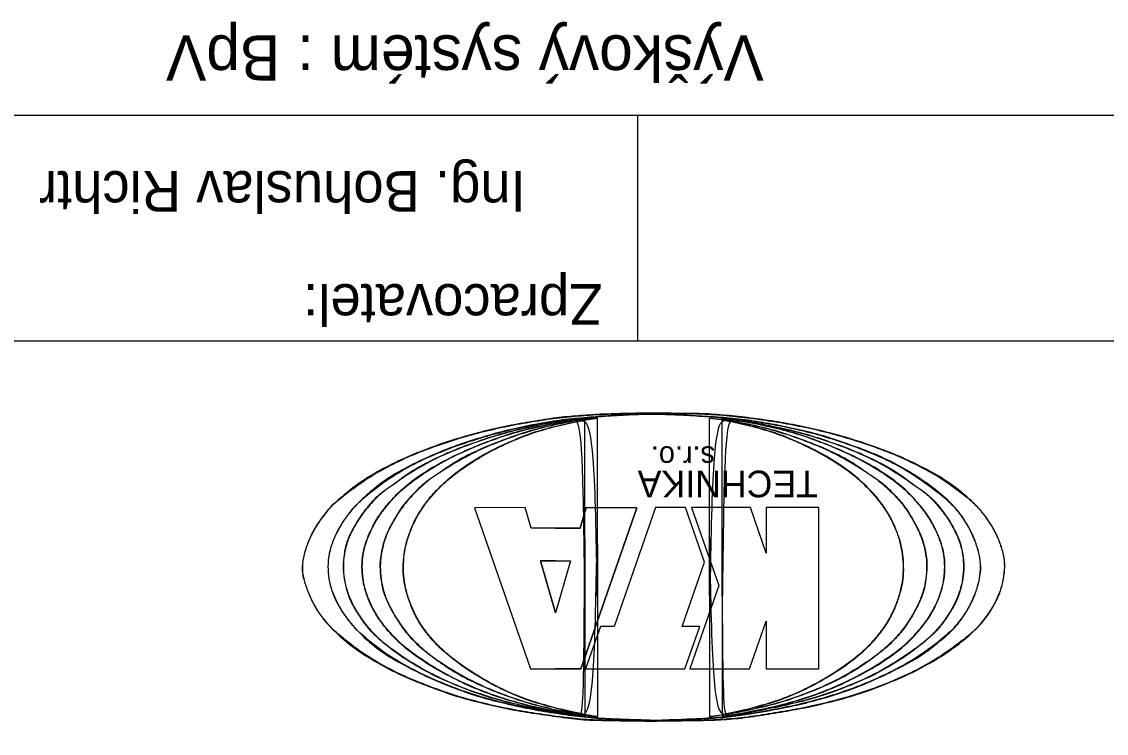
# Model space of a CAD drawing. Extents: x -728476.8 to -728424.3, y -1073086.9 to -1073012.7.
# Drawn here: x -728468.69 to -728456.69, y -1073042.49 to -1073034.62 of the extents above; entities that cross this region are included whole.
import ezdxf

# ---------------------------------------------------------------- set-up
doc = ezdxf.new("R2010")
doc.units = 0
doc.layers.add('A1_OBVOD Spravy železnic', color=7, linetype='Continuous')
doc.layers.add('B6_JŽM', color=7, linetype='Continuous')

msp = doc.modelspace()

# ---------------------------------------------------------------- linework, layer by layer
at = {"layer": 'A1_OBVOD Spravy železnic'}
for p, q in [((-728461.876, -1073035.654), (-728461.876, -1073038.154)), ((-728429.288, -1073038.154), (-728471.788, -1073038.154))]:
    msp.add_line(p, q, dxfattribs=at)
msp.add_lwpolyline([(-728429.288, -1073048.154), (-728471.788, -1073048.154), (-728471.788, -1073035.654), (-728429.288, -1073035.654)], close=True, dxfattribs=at)
at = {"layer": 'B6_JŽM'}
for p, q in [((-728462.947, -1073040.587), (-728462.781, -1073040.587)), ((-728462.781, -1073041.161), (-728462.947, -1073040.587))]:
    msp.add_line(p, q, dxfattribs=at)
for points in [[(-728462.781, -1073040.225), (-728463.051, -1073040.225), (-728463.117, -1073039.997), (-728463.68, -1073039.998), (-728463.059, -1073041.782), (-728462.781, -1073041.782)], [(-728462.781, -1073040.225), (-728463.051, -1073040.225), (-728463.117, -1073039.997), (-728463.68, -1073039.998), (-728463.059, -1073041.782), (-728462.781, -1073041.782)], [(-728462.781, -1073040.225), (-728462.51, -1073040.225), (-728462.444, -1073039.997), (-728461.881, -1073039.998), (-728462.502, -1073041.782), (-728462.781, -1073041.782)], [(-728462.781, -1073041.782), (-728462.502, -1073041.782), (-728461.881, -1073039.998), (-728462.444, -1073039.997), (-728462.51, -1073040.225), (-728462.781, -1073040.225)], [(-728461.351, -1073041.782), (-728461.187, -1073041.311), (-728461.381, -1073041.311), (-728461.134, -1073040.601), (-728461.344, -1073039.997), (-728461.676, -1073039.997), (-728462.133, -1073041.311), (-728462.284, -1073041.311), (-728462.449, -1073041.782), (-728461.351, -1073041.782)], [(-728461.351, -1073041.782), (-728461.187, -1073041.311), (-728461.381, -1073041.311), (-728461.134, -1073040.601), (-728461.344, -1073039.997), (-728461.676, -1073039.997), (-728462.133, -1073041.311), (-728462.284, -1073041.311), (-728462.449, -1073041.782), (-728461.351, -1073041.782)], [(-728459.867, -1073041.782), (-728459.867, -1073039.997), (-728460.451, -1073039.997), (-728460.451, -1073040.5), (-728460.626, -1073039.997), (-728461.276, -1073039.997), (-728460.976, -1073040.859), (-728461.297, -1073041.782), (-728460.635, -1073041.782), (-728460.451, -1073041.253), (-728460.451, -1073041.782), (-728459.867, -1073041.782)], [(-728459.867, -1073041.782), (-728459.867, -1073039.997), (-728460.451, -1073039.997), (-728460.451, -1073040.5), (-728460.626, -1073039.997), (-728461.276, -1073039.997), (-728460.976, -1073040.859), (-728461.297, -1073041.782), (-728460.635, -1073041.782), (-728460.451, -1073041.253), (-728460.451, -1073041.782), (-728459.867, -1073041.782)], [(-728462.781, -1073040.587), (-728462.947, -1073040.587), (-728462.781, -1073041.161)], [(-728462.781, -1073040.587), (-728462.615, -1073040.587), (-728462.781, -1073041.161)], [(-728462.781, -1073040.587), (-728462.615, -1073040.587), (-728462.781, -1073041.161)]]:
    msp.add_lwpolyline(points, dxfattribs=at)
for points in [[(-728462.313, -1073038.965), (-728462.376, -1073038.969), (-728462.529, -1073038.98), (-728462.771, -1073039), (-728463.038, -1073039.044), (-728463.307, -1073039.089), (-728463.576, -1073039.15), (-728463.845, -1073039.224), (-728464.113, -1073039.313), (-728464.382, -1073039.416), (-728464.653, -1073039.542), (-728464.929, -1073039.699), (-728465.125, -1073039.86), (-728465.283, -1073039.992), (-728465.368, -1073040.112), (-728465.461, -1073040.242), (-728465.521, -1073040.38), (-728465.567, -1073040.514), (-728465.592, -1073040.65), (-728465.574, -1073040.789), (-728465.523, -1073040.921), (-728465.466, -1073041.059), (-728465.382, -1073041.195), (-728465.284, -1073041.308), (-728465.134, -1073041.456), (-728464.928, -1073041.611), (-728464.655, -1073041.771), (-728464.385, -1073041.901), (-728464.114, -1073042.001), (-728463.847, -1073042.097), (-728463.576, -1073042.164), (-728463.308, -1073042.226), (-728463.038, -1073042.272), (-728462.769, -1073042.307), (-728462.502, -1073042.348), (-728462.234, -1073042.351), (-728461.966, -1073042.357), (-728461.788, -1073042.358), (-728461.698, -1073042.359)], [(-728461.698, -1073042.359), (-728461.395, -1073042.355), (-728461.162, -1073042.352), (-728460.894, -1073042.341), (-728460.626, -1073042.312), (-728460.358, -1073042.27), (-728460.09, -1073042.224), (-728459.822, -1073042.166), (-728459.554, -1073042.096), (-728459.285, -1073042.009), (-728459.017, -1073041.902), (-728458.751, -1073041.779), (-728458.482, -1073041.62), (-728458.214, -1073041.418), (-728458.11, -1073041.321), (-728458.001, -1073041.186), (-728457.919, -1073041.053), (-728457.859, -1073040.918), (-728457.827, -1073040.785), (-728457.811, -1073040.651), (-728457.825, -1073040.519), (-728457.866, -1073040.383), (-728457.926, -1073040.249), (-728458.01, -1073040.115), (-728458.118, -1073039.981), (-728458.214, -1073039.891), (-728458.482, -1073039.688), (-728458.75, -1073039.537), (-728459.015, -1073039.413), (-728459.286, -1073039.311), (-728459.555, -1073039.224), (-728459.821, -1073039.151), (-728460.088, -1073039.092), (-728460.357, -1073039.043), (-728460.626, -1073039.005), (-728460.895, -1073038.975), (-728461.16, -1073038.957), (-728461.43, -1073038.954), (-728461.698, -1073038.95), (-728461.966, -1073038.954), (-728462.235, -1073038.961), (-728462.503, -1073038.978), (-728462.769, -1073039.003), (-728463.038, -1073039.044), (-728463.306, -1073039.092), (-728463.574, -1073039.152), (-728463.843, -1073039.226), (-728464.111, -1073039.314), (-728464.379, -1073039.418), (-728464.645, -1073039.543), (-728464.915, -1073039.701), (-728465.185, -1073039.91), (-728465.265, -1073039.981), (-728465.37, -1073040.115), (-728465.458, -1073040.248), (-728465.52, -1073040.383), (-728465.564, -1073040.516), (-728465.585, -1073040.651), (-728465.57, -1073040.784), (-728465.523, -1073040.919), (-728465.463, -1073041.056), (-728465.383, -1073041.186), (-728465.269, -1073041.321), (-728465.187, -1073041.402), (-728464.916, -1073041.612), (-728464.648, -1073041.77), (-728464.382, -1073041.897), (-728464.112, -1073042.001), (-728463.843, -1073042.093), (-728463.576, -1073042.163), (-728463.306, -1073042.224), (-728463.037, -1073042.27), (-728462.768, -1073042.308), (-728462.502, -1073042.342), (-728462.234, -1073042.352), (-728461.967, -1073042.356), (-728461.698, -1073042.359), (-728461.698, -1073042.359), (-728461.698, -1073042.359)], [(-728461.698, -1073042.352), (-728461.788, -1073042.348), (-728461.967, -1073042.341), (-728462.235, -1073042.338), (-728462.503, -1073042.309), (-728462.771, -1073042.275), (-728463.04, -1073042.23), (-728463.307, -1073042.171), (-728463.578, -1073042.107), (-728463.845, -1073042.015), (-728464.116, -1073041.912), (-728464.383, -1073041.78), (-728464.662, -1073041.63), (-728464.867, -1073041.466), (-728465.02, -1073041.314), (-728465.116, -1073041.192), (-728465.198, -1073041.057), (-728465.26, -1073040.922), (-728465.292, -1073040.785), (-728465.303, -1073040.65), (-728465.293, -1073040.514), (-728465.252, -1073040.379), (-728465.192, -1073040.244), (-728465.107, -1073040.11), (-728465.016, -1073039.991), (-728464.861, -1073039.846), (-728464.662, -1073039.681), (-728464.385, -1073039.525), (-728464.114, -1073039.4), (-728463.845, -1073039.295), (-728463.576, -1073039.211), (-728463.308, -1073039.136), (-728463.039, -1073039.081), (-728462.771, -1073039.032), (-728462.502, -1073039.005), (-728462.234, -1073038.982), (-728461.967, -1073038.965), (-728461.698, -1073038.956), (-728461.43, -1073038.967), (-728461.162, -1073038.986), (-728460.893, -1073039), (-728460.625, -1073039.032), (-728460.356, -1073039.076), (-728460.088, -1073039.133), (-728459.818, -1073039.199), (-728459.552, -1073039.291), (-728459.281, -1073039.388), (-728459.009, -1073039.512), (-728458.74, -1073039.675), (-728458.528, -1073039.835), (-728458.367, -1073039.983), (-728458.27, -1073040.109), (-728458.191, -1073040.245), (-728458.13, -1073040.38), (-728458.093, -1073040.515), (-728458.069, -1073040.651), (-728458.09, -1073040.787), (-728458.125, -1073040.922), (-728458.181, -1073041.057), (-728458.261, -1073041.192), (-728458.357, -1073041.324), (-728458.525, -1073041.473), (-728458.736, -1073041.641), (-728459.014, -1073041.789), (-728459.281, -1073041.919), (-728459.55, -1073042.024), (-728459.819, -1073042.109), (-728460.088, -1073042.178), (-728460.317, -1073042.224), (-728460.497, -1073042.257), (-728460.675, -1073042.285), (-728460.893, -1073042.317), (-728461.162, -1073042.334), (-728461.43, -1073042.345), (-728461.609, -1073042.349), (-728461.698, -1073042.352)], [(-728461.698, -1073042.352), (-728461.43, -1073042.344), (-728461.162, -1073042.333), (-728460.894, -1073042.314), (-728460.626, -1073042.277), (-728460.506, -1073042.258), (-728460.358, -1073042.231), (-728460.09, -1073042.176), (-728459.822, -1073042.107), (-728459.553, -1073042.021), (-728459.285, -1073041.916), (-728459.017, -1073041.789), (-728458.751, -1073041.639), (-728458.482, -1073041.434), (-728458.363, -1073041.321), (-728458.26, -1073041.186), (-728458.183, -1073041.053), (-728458.127, -1073040.918), (-728458.092, -1073040.785), (-728458.077, -1073040.651), (-728458.095, -1073040.517), (-728458.133, -1073040.384), (-728458.192, -1073040.249), (-728458.27, -1073040.115), (-728458.376, -1073039.98), (-728458.482, -1073039.879), (-728458.75, -1073039.675), (-728459.017, -1073039.514), (-728459.285, -1073039.391), (-728459.553, -1073039.291), (-728459.821, -1073039.203), (-728460.089, -1073039.134), (-728460.357, -1073039.078), (-728460.626, -1073039.034), (-728460.894, -1073039.003), (-728461.162, -1073038.985), (-728461.43, -1073038.968), (-728461.698, -1073038.96), (-728461.966, -1073038.967), (-728462.235, -1073038.983), (-728462.501, -1073039.006), (-728462.769, -1073039.035), (-728463.038, -1073039.082), (-728463.306, -1073039.139), (-728463.574, -1073039.212), (-728463.843, -1073039.298), (-728464.111, -1073039.402), (-728464.379, -1073039.526), (-728464.647, -1073039.683), (-728464.915, -1073039.897), (-728465.001, -1073039.981), (-728465.108, -1073040.115), (-728465.19, -1073040.248), (-728465.251, -1073040.383), (-728465.289, -1073040.516), (-728465.3, -1073040.649), (-728465.288, -1073040.785), (-728465.256, -1073040.918), (-728465.197, -1073041.052), (-728465.116, -1073041.186), (-728465.009, -1073041.321), (-728464.915, -1073041.416), (-728464.647, -1073041.628), (-728464.379, -1073041.78), (-728464.111, -1073041.909), (-728463.843, -1073042.014), (-728463.575, -1073042.103), (-728463.307, -1073042.17), (-728463.039, -1073042.228), (-728462.77, -1073042.273), (-728462.502, -1073042.308), (-728462.235, -1073042.334), (-728461.967, -1073042.342), (-728461.698, -1073042.352), (-728461.698, -1073042.352), (-728461.698, -1073042.352)], [(-728462.458, -1073039.009), (-728462.509, -1073039.014), (-728462.614, -1073039.022), (-728462.809, -1073039.052), (-728463.041, -1073039.1), (-728463.312, -1073039.158), (-728463.579, -1073039.243), (-728463.848, -1073039.336), (-728464.118, -1073039.453), (-728464.392, -1073039.6), (-728464.582, -1073039.75), (-728464.752, -1073039.861), (-728464.852, -1073039.974), (-728464.954, -1073040.111), (-728465.034, -1073040.245), (-728465.096, -1073040.378), (-728465.123, -1073040.516), (-728465.138, -1073040.65), (-728465.123, -1073040.786), (-728465.092, -1073040.922), (-728465.04, -1073041.06), (-728464.957, -1073041.19), (-728464.861, -1073041.332), (-728464.751, -1073041.438), (-728464.591, -1073041.568), (-728464.389, -1073041.71), (-728464.118, -1073041.863), (-728463.846, -1073041.976), (-728463.579, -1073042.078), (-728463.309, -1073042.151), (-728463.038, -1073042.212), (-728462.771, -1073042.265), (-728462.577, -1073042.299), (-728462.473, -1073042.306), (-728462.459, -1073042.306)], [(-728462.458, -1073039.009), (-728462.611, -1073039.024), (-728462.772, -1073039.048), (-728463.04, -1073039.1), (-728463.309, -1073039.162), (-728463.578, -1073039.244), (-728463.845, -1073039.339), (-728464.112, -1073039.454), (-728464.381, -1073039.603), (-728464.65, -1073039.794), (-728464.722, -1073039.845), (-728464.854, -1073039.98), (-728464.955, -1073040.117), (-728465.033, -1073040.249), (-728465.091, -1073040.381), (-728465.121, -1073040.517), (-728465.133, -1073040.651), (-728465.121, -1073040.783), (-728465.09, -1073040.919), (-728465.037, -1073041.054), (-728464.958, -1073041.187), (-728464.862, -1073041.321), (-728464.725, -1073041.458), (-728464.652, -1073041.518), (-728464.381, -1073041.709), (-728464.11, -1073041.86), (-728463.843, -1073041.976), (-728463.578, -1073042.073), (-728463.304, -1073042.15), (-728463.039, -1073042.21), (-728462.769, -1073042.264), (-728462.501, -1073042.304), (-728462.459, -1073042.306), (-728462.458, -1073039.009), (-728462.459, -1073042.306)], [(-728462.459, -1073042.306), (-728462.555, -1073042.292), (-728462.749, -1073042.263), (-728463.033, -1073042.204), (-728463.31, -1073042.128), (-728463.58, -1073042.039), (-728463.848, -1073041.921), (-728464.118, -1073041.779), (-728464.355, -1073041.624), (-728464.541, -1073041.469), (-728464.665, -1073041.326), (-728464.763, -1073041.193), (-728464.835, -1073041.057), (-728464.887, -1073040.922), (-728464.917, -1073040.786), (-728464.927, -1073040.65), (-728464.917, -1073040.515), (-728464.883, -1073040.379), (-728464.825, -1073040.246), (-728464.755, -1073040.108), (-728464.654, -1073039.976), (-728464.531, -1073039.837), (-728464.352, -1073039.682), (-728464.118, -1073039.53), (-728463.846, -1073039.393), (-728463.577, -1073039.279), (-728463.31, -1073039.183), (-728463.04, -1073039.111), (-728462.797, -1073039.062), (-728462.603, -1073039.029), (-728462.498, -1073039.015), (-728462.458, -1073039.009)], [(-728462.459, -1073042.306), (-728462.748, -1073042.26), (-728463.038, -1073042.2), (-728463.308, -1073042.126), (-728463.577, -1073042.035), (-728463.842, -1073041.92), (-728464.11, -1073041.778), (-728464.379, -1073041.6), (-728464.547, -1073041.455), (-728464.667, -1073041.32), (-728464.762, -1073041.187), (-728464.833, -1073041.055), (-728464.884, -1073040.919), (-728464.914, -1073040.783), (-728464.923, -1073040.651), (-728464.913, -1073040.516), (-728464.88, -1073040.383), (-728464.825, -1073040.249), (-728464.753, -1073040.114), (-728464.655, -1073039.981), (-728464.536, -1073039.847), (-728464.376, -1073039.708), (-728464.111, -1073039.532), (-728463.842, -1073039.394), (-728463.574, -1073039.28), (-728463.306, -1073039.186), (-728463.039, -1073039.114), (-728462.77, -1073039.058), (-728462.58, -1073039.027), (-728462.458, -1073039.009), (-728462.459, -1073042.306), (-728462.458, -1073039.009)], [(-728462.318, -1073039.005), (-728462.379, -1073039.011), (-728462.532, -1073039.024), (-728462.771, -1073039.075), (-728463.042, -1073039.136), (-728463.309, -1073039.228), (-728463.579, -1073039.332), (-728463.853, -1073039.462), (-728464.055, -1073039.605), (-728464.235, -1073039.724), (-728464.353, -1073039.841), (-728464.475, -1073039.972), (-728464.558, -1073040.113), (-728464.635, -1073040.244), (-728464.687, -1073040.379), (-728464.715, -1073040.515), (-728464.73, -1073040.65), (-728464.714, -1073040.785), (-728464.693, -1073040.922), (-728464.637, -1073041.056), (-728464.565, -1073041.19), (-728464.478, -1073041.327), (-728464.365, -1073041.464), (-728464.237, -1073041.578), (-728464.062, -1073041.71), (-728463.851, -1073041.848), (-728463.58, -1073041.981), (-728463.31, -1073042.086), (-728463.042, -1073042.175), (-728462.772, -1073042.236), (-728462.532, -1073042.286), (-728462.379, -1073042.303), (-728462.318, -1073042.31)], [(-728462.318, -1073039.005), (-728462.502, -1073039.024), (-728462.771, -1073039.075), (-728463.037, -1073039.14), (-728463.306, -1073039.229), (-728463.575, -1073039.335), (-728463.842, -1073039.466), (-728464.111, -1073039.641), (-728464.212, -1073039.712), (-728464.358, -1073039.848), (-728464.473, -1073039.98), (-728464.559, -1073040.115), (-728464.633, -1073040.249), (-728464.684, -1073040.383), (-728464.713, -1073040.514), (-728464.725, -1073040.65), (-728464.713, -1073040.786), (-728464.688, -1073040.918), (-728464.637, -1073041.051), (-728464.564, -1073041.188), (-728464.479, -1073041.321), (-728464.367, -1073041.455), (-728464.22, -1073041.589), (-728464.11, -1073041.673), (-728463.842, -1073041.846), (-728463.576, -1073041.979), (-728463.306, -1073042.085), (-728463.04, -1073042.171), (-728462.772, -1073042.235), (-728462.502, -1073042.287), (-728462.318, -1073042.31), (-728462.318, -1073039.005), (-728462.318, -1073042.31)], [(-728462.318, -1073042.31), (-728462.379, -1073042.301), (-728462.532, -1073042.279), (-728462.772, -1073042.22), (-728463.043, -1073042.148), (-728463.313, -1073042.042), (-728463.583, -1073041.903), (-728463.819, -1073041.749), (-728464.012, -1073041.6), (-728464.148, -1073041.461), (-728464.254, -1073041.327), (-728464.335, -1073041.191), (-728464.393, -1073041.055), (-728464.437, -1073040.921), (-728464.465, -1073040.786), (-728464.469, -1073040.651), (-728464.461, -1073040.516), (-728464.435, -1073040.38), (-728464.387, -1073040.247), (-728464.328, -1073040.11), (-728464.243, -1073039.977), (-728464.137, -1073039.841), (-728464.001, -1073039.708), (-728463.817, -1073039.555), (-728463.583, -1073039.408), (-728463.312, -1073039.274), (-728463.043, -1073039.165), (-728462.773, -1073039.09), (-728462.531, -1073039.039), (-728462.379, -1073039.015), (-728462.318, -1073039.005)], [(-728462.318, -1073042.31), (-728462.502, -1073042.281), (-728462.77, -1073042.219), (-728463.039, -1073042.143), (-728463.307, -1073042.04), (-728463.575, -1073041.902), (-728463.843, -1073041.728), (-728464.019, -1073041.588), (-728464.149, -1073041.455), (-728464.254, -1073041.32), (-728464.333, -1073041.187), (-728464.392, -1073041.053), (-728464.435, -1073040.919), (-728464.461, -1073040.784), (-728464.467, -1073040.651), (-728464.458, -1073040.517), (-728464.432, -1073040.382), (-728464.386, -1073040.249), (-728464.326, -1073040.115), (-728464.243, -1073039.981), (-728464.139, -1073039.849), (-728464.004, -1073039.714), (-728463.843, -1073039.581), (-728463.575, -1073039.41), (-728463.307, -1073039.276), (-728463.04, -1073039.169), (-728462.769, -1073039.092), (-728462.502, -1073039.036), (-728462.318, -1073039.005), (-728462.318, -1073042.31), (-728462.318, -1073039.005)], [(-728461.698, -1073042.359), (-728461.597, -1073042.357), (-728461.419, -1073042.355), (-728461.15, -1073042.352), (-728460.893, -1073042.344), (-728460.625, -1073042.315), (-728460.358, -1073042.27), (-728460.089, -1073042.226), (-728459.82, -1073042.168), (-728459.551, -1073042.099), (-728459.282, -1073042.011), (-728459.015, -1073041.903), (-728458.743, -1073041.781), (-728458.472, -1073041.62), (-728458.261, -1073041.462), (-728458.1, -1073041.316), (-728458.001, -1073041.193), (-728457.918, -1073041.057), (-728457.855, -1073040.923), (-728457.825, -1073040.786), (-728457.805, -1073040.652), (-728457.822, -1073040.515), (-728457.864, -1073040.38), (-728457.924, -1073040.244), (-728458.012, -1073040.11), (-728458.106, -1073039.988), (-728458.264, -1073039.845), (-728458.469, -1073039.686), (-728458.744, -1073039.536), (-728459.012, -1073039.41), (-728459.283, -1073039.31), (-728459.552, -1073039.222), (-728459.82, -1073039.149), (-728460.088, -1073039.09), (-728460.356, -1073039.041), (-728460.626, -1073039.004), (-728460.893, -1073038.974), (-728461.162, -1073038.953), (-728461.43, -1073038.956), (-728461.698, -1073038.947), (-728461.966, -1073038.955), (-728462.171, -1073038.958), (-728462.287, -1073038.964), (-728462.313, -1073038.965)], [(-728461.079, -1073039.005), (-728461.017, -1073039.011), (-728460.864, -1073039.024), (-728460.625, -1073039.075), (-728460.355, -1073039.136), (-728460.088, -1073039.228), (-728459.817, -1073039.332), (-728459.543, -1073039.462), (-728459.341, -1073039.605), (-728459.162, -1073039.724), (-728459.043, -1073039.841), (-728458.921, -1073039.972), (-728458.839, -1073040.113), (-728458.762, -1073040.244), (-728458.71, -1073040.379), (-728458.681, -1073040.515), (-728458.667, -1073040.65), (-728458.683, -1073040.785), (-728458.704, -1073040.922), (-728458.759, -1073041.056), (-728458.831, -1073041.19), (-728458.918, -1073041.327), (-728459.031, -1073041.464), (-728459.16, -1073041.578), (-728459.334, -1073041.71), (-728459.545, -1073041.848), (-728459.817, -1073041.981), (-728460.086, -1073042.086), (-728460.354, -1073042.175), (-728460.624, -1073042.236), (-728460.865, -1073042.286), (-728461.017, -1073042.303), (-728461.079, -1073042.31)], [(-728461.079, -1073042.31), (-728461.017, -1073042.301), (-728460.865, -1073042.279), (-728460.625, -1073042.22), (-728460.354, -1073042.148), (-728460.083, -1073042.042), (-728459.814, -1073041.903), (-728459.577, -1073041.749), (-728459.384, -1073041.6), (-728459.249, -1073041.461), (-728459.142, -1073041.327), (-728459.061, -1073041.191), (-728459.003, -1073041.055), (-728458.96, -1073040.921), (-728458.932, -1073040.786), (-728458.928, -1073040.651), (-728458.936, -1073040.516), (-728458.962, -1073040.38), (-728459.01, -1073040.247), (-728459.069, -1073040.11), (-728459.153, -1073039.977), (-728459.26, -1073039.841), (-728459.395, -1073039.708), (-728459.579, -1073039.555), (-728459.813, -1073039.408), (-728460.084, -1073039.274), (-728460.353, -1073039.165), (-728460.624, -1073039.09), (-728460.866, -1073039.039), (-728461.017, -1073039.015), (-728461.079, -1073039.005)], [(-728461.079, -1073039.005), (-728460.894, -1073039.024), (-728460.625, -1073039.075), (-728460.359, -1073039.14), (-728460.09, -1073039.229), (-728459.821, -1073039.335), (-728459.554, -1073039.466), (-728459.286, -1073039.641), (-728459.185, -1073039.712), (-728459.039, -1073039.848), (-728458.923, -1073039.98), (-728458.838, -1073040.115), (-728458.764, -1073040.249), (-728458.713, -1073040.383), (-728458.684, -1073040.514), (-728458.672, -1073040.65), (-728458.684, -1073040.786), (-728458.709, -1073040.918), (-728458.76, -1073041.051), (-728458.832, -1073041.188), (-728458.918, -1073041.321), (-728459.029, -1073041.455), (-728459.177, -1073041.589), (-728459.287, -1073041.673), (-728459.554, -1073041.846), (-728459.821, -1073041.979), (-728460.09, -1073042.085), (-728460.356, -1073042.171), (-728460.625, -1073042.235), (-728460.894, -1073042.287), (-728461.079, -1073042.31), (-728461.079, -1073039.005), (-728461.079, -1073042.31)], [(-728461.079, -1073042.31), (-728460.894, -1073042.281), (-728460.627, -1073042.219), (-728460.357, -1073042.143), (-728460.09, -1073042.04), (-728459.821, -1073041.902), (-728459.554, -1073041.728), (-728459.378, -1073041.588), (-728459.248, -1073041.455), (-728459.142, -1073041.32), (-728459.063, -1073041.187), (-728459.005, -1073041.053), (-728458.962, -1073040.919), (-728458.936, -1073040.784), (-728458.93, -1073040.651), (-728458.939, -1073040.517), (-728458.965, -1073040.382), (-728459.01, -1073040.249), (-728459.07, -1073040.115), (-728459.154, -1073039.981), (-728459.258, -1073039.849), (-728459.392, -1073039.714), (-728459.553, -1073039.581), (-728459.821, -1073039.41), (-728460.089, -1073039.276), (-728460.357, -1073039.169), (-728460.628, -1073039.092), (-728460.894, -1073039.036), (-728461.079, -1073039.005), (-728461.079, -1073042.31), (-728461.079, -1073039.005)], [(-728460.938, -1073042.306), (-728460.841, -1073042.292), (-728460.647, -1073042.263), (-728460.363, -1073042.204), (-728460.087, -1073042.128), (-728459.816, -1073042.039), (-728459.549, -1073041.921), (-728459.278, -1073041.779), (-728459.041, -1073041.624), (-728458.855, -1073041.469), (-728458.731, -1073041.326), (-728458.634, -1073041.193), (-728458.562, -1073041.057), (-728458.51, -1073040.922), (-728458.479, -1073040.786), (-728458.47, -1073040.65), (-728458.48, -1073040.515), (-728458.514, -1073040.379), (-728458.571, -1073040.246), (-728458.642, -1073040.108), (-728458.743, -1073039.976), (-728458.865, -1073039.837), (-728459.045, -1073039.682), (-728459.278, -1073039.53), (-728459.55, -1073039.393), (-728459.819, -1073039.279), (-728460.087, -1073039.183), (-728460.356, -1073039.111), (-728460.599, -1073039.062), (-728460.794, -1073039.029), (-728460.898, -1073039.015), (-728460.939, -1073039.009)], [(-728460.939, -1073039.009), (-728460.888, -1073039.014), (-728460.782, -1073039.022), (-728460.588, -1073039.052), (-728460.356, -1073039.1), (-728460.085, -1073039.158), (-728459.817, -1073039.243), (-728459.548, -1073039.336), (-728459.278, -1073039.453), (-728459.004, -1073039.6), (-728458.814, -1073039.75), (-728458.645, -1073039.861), (-728458.544, -1073039.974), (-728458.442, -1073040.111), (-728458.363, -1073040.245), (-728458.301, -1073040.378), (-728458.274, -1073040.516), (-728458.259, -1073040.65), (-728458.273, -1073040.786), (-728458.304, -1073040.922), (-728458.356, -1073041.06), (-728458.44, -1073041.19), (-728458.535, -1073041.332), (-728458.645, -1073041.438), (-728458.805, -1073041.568), (-728459.007, -1073041.71), (-728459.279, -1073041.863), (-728459.55, -1073041.976), (-728459.818, -1073042.078), (-728460.088, -1073042.151), (-728460.358, -1073042.212), (-728460.626, -1073042.265), (-728460.819, -1073042.299), (-728460.924, -1073042.306), (-728460.938, -1073042.306)], [(-728460.939, -1073039.009), (-728460.785, -1073039.024), (-728460.625, -1073039.048), (-728460.357, -1073039.1), (-728460.087, -1073039.162), (-728459.818, -1073039.244), (-728459.552, -1073039.339), (-728459.285, -1073039.454), (-728459.016, -1073039.603), (-728458.746, -1073039.794), (-728458.674, -1073039.845), (-728458.543, -1073039.98), (-728458.441, -1073040.117), (-728458.364, -1073040.249), (-728458.306, -1073040.381), (-728458.275, -1073040.517), (-728458.263, -1073040.651), (-728458.275, -1073040.783), (-728458.307, -1073040.919), (-728458.359, -1073041.054), (-728458.438, -1073041.187), (-728458.534, -1073041.321), (-728458.671, -1073041.458), (-728458.745, -1073041.518), (-728459.016, -1073041.709), (-728459.287, -1073041.86), (-728459.554, -1073041.976), (-728459.818, -1073042.073), (-728460.092, -1073042.15), (-728460.358, -1073042.21), (-728460.627, -1073042.264), (-728460.896, -1073042.304), (-728460.938, -1073042.306), (-728460.939, -1073039.009), (-728460.938, -1073042.306)], [(-728460.938, -1073042.306), (-728460.649, -1073042.26), (-728460.358, -1073042.2), (-728460.089, -1073042.126), (-728459.82, -1073042.035), (-728459.554, -1073041.92), (-728459.286, -1073041.778), (-728459.017, -1073041.6), (-728458.849, -1073041.455), (-728458.729, -1073041.32), (-728458.635, -1073041.187), (-728458.564, -1073041.055), (-728458.512, -1073040.919), (-728458.482, -1073040.783), (-728458.473, -1073040.651), (-728458.483, -1073040.516), (-728458.516, -1073040.383), (-728458.572, -1073040.249), (-728458.644, -1073040.114), (-728458.741, -1073039.981), (-728458.861, -1073039.847), (-728459.02, -1073039.708), (-728459.285, -1073039.532), (-728459.555, -1073039.394), (-728459.822, -1073039.28), (-728460.091, -1073039.186), (-728460.357, -1073039.114), (-728460.626, -1073039.058), (-728460.817, -1073039.027), (-728460.939, -1073039.009), (-728460.938, -1073042.306), (-728460.939, -1073039.009)]]:
    msp.add_open_spline(points, degree=3, dxfattribs=at)

# ---------------------------------------------------------------- texts
at = {"layer": 'A1_OBVOD Spravy železnic'}
for s, height, p in [('Výškový systém : BpV', 0.5, (-728460.478, -1073034.77)), ('Ing. Bohuslav Richtr', 0.45, (-728463.112, -1073036.273)), ('Zpracovatel:', 0.45, (-728462.263, -1073037.523))]:
    msp.add_text(s, height=height, rotation=180, dxfattribs=at).set_placement(p)
at = {"layer": 'B6_JŽM'}
for s, height, p in [('s.r.o.', 0.2386, (-728461.018, -1073039.318)), ('TECHNIKA', 0.2949, (-728459.879, -1073039.587))]:
    msp.add_text(s, height=height, rotation=180, dxfattribs=at).set_placement(p)

doc.saveas('drawing.dxf')
